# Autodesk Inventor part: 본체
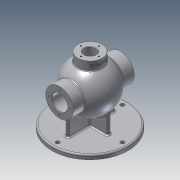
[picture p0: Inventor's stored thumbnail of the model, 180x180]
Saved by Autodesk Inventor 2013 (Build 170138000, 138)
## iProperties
Created: 2020-08
Part Number: 본체
Material: 알루미늄 6061
Document SubType Name: Sheet Metal
Designer: CADCOM
Density: 2.71 g/cm^3
Sheet Metal Rule: Default_mm
Mass: 1759.19 g
Surface Area: 1342.58 cm^2
Volume: 649.146 cm^3
Author: CADCOM
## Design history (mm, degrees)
sketch "스케치2"
  geometry: L1 (-27.958, -45.026)-(27.958, 45.026); A1 r 53 centre (0, 0) between (-27.958, -45.026) and (27.958, 45.026); 1 further point
  constraints: 2 end point, 2 point on circle, 1 centre point, 1 coincident, 1 midpoint
  dimensions: "d3" = 106 diameter of A1
revolve "회전2" sketch "스케치2" stored, may be unused: angle "d4" = 90 deg
node "작업 평면1"
sketch "스케치3"
  geometry: C1 r 31 at (0, 0); 1 further point
  constraints: 1 centre point, 1 coincident
  dimensions: "d6" = 62 diameter of C1
extrude "돌출1" join sketch "스케치3" stored distance "d7" = 10; taper "d8" = 0 deg
node "작업 평면2"
sketch "스케치4"
  geometry: C1 r 31 at (0, 0); 1 further point
  constraints: 1 centre point, 1 coincident
  dimensions: "d10" = 62 diameter of C1
extrude "돌출2" join sketch "스케치4" stored distance "d11" = 10; taper "d12" = 0 deg
sketch "스케치5"
  geometry: L1 (32.002, -28.72)-(-32.002, 28.72); A1 r 43 centre (0, 0) between (32.002, -28.72) and (-32.002, 28.72); 1 further point
  constraints: 2 end point, 2 point on circle, 1 centre point, 1 coincident, 1 midpoint
  dimensions: "d13" = 86 diameter of A1
revolve "회전3" sketch "스케치5" stored, may be unused: angle "d14" = 90 deg
sketch "스케치6"
  geometry: C1 r 31 at (0, 0) reference; C2 r 17.5 at (0, 0)
  constraints: 1 centre point, 1 coincident
  dimensions: "d15" = 35 diameter of C2
extrude "돌출3" cut sketch "스케치6" stored distance "d16" = 10; taper "d17" = 0 deg
node "작업 평면3"
sketch "스케치7"
  geometry: C1 r 27 at (0, 0); 1 further point
  constraints: 1 centre point, 1 coincident
  dimensions: "d19" = 54 diameter of C1
extrude "돌출4" join sketch "스케치7" stored distance "d20" = 10; taper "d21" = 0 deg
sketch "스케치8"
  geometry: C1 r 27 at (0, 0) reference; C2 r 13 at (0, 0)
  constraints: 1 centre point, 1 coincident
  dimensions: "d22" = 26 diameter of C2
extrude "돌출5" cut sketch "스케치8" stored distance "d23" = 10; taper "d24" = 0 deg
sketch "스케치9" dims "d25" = 48
  geometry: C1 r 17.5 at (0, 0) reference; C2 r 31 at (0, 0) reference; 2 further points
  constraints: 2 vertical alignment, 1 coincident, 2 other
hole "구멍1" sketch "스케치9" at (0, 24) diameter "d26" = 3.242; stored, may be unused: countersink angle "d30" = 90 deg, drill point angle "d32" = 118 deg; dims "d27" = 12, "d28" = 4, "d29" = 2, "d31" = 15
sketch "스케치10" dims "d36" = 40
  geometry: C1 r 13 at (0, 0) reference; C2 r 27 at (0, 0) reference; 2 further points
  constraints: 2 vertical alignment, 1 coincident, 2 other
hole "구멍2" sketch "스케치10" at (0, 20) diameter "d37" = 3.242; stored, may be unused: countersink angle "d41" = 90 deg, drill point angle "d43" = 118 deg; dims "d38" = 12, "d39" = 4, "d40" = 2, "d42" = 15
node "작업 평면4"
sketch "스케치11"
  geometry: C1 r 85 at (0, 0); 1 further point
  constraints: 1 centre point, 1 coincident
  dimensions: "d48" = 170 diameter of C1
extrude "돌출6" join sketch "스케치11" distance "d49" = 10; taper "d50" = 0 deg
sketch "스케치12"
  geometry: L1 (-52, 4)-(52, 4); L2 (52, 4)-(52, -4); L3 (52, -4)-(-52, -4); L4 (-52, -4)-(-52, 4); L5 (-4, 43)-(4, 43); L6 (4, 43)-(4, -43); L7 (4, -43)-(-4, -43); L8 (-4, -43)-(-4, 43); C1 r 85 at (0, 0) reference
  constraints: 16 end point, 4 parallel, 2 horizontal, 2 perpendicular
  dimensions: "d51" = 104 distance of L2.end L3.end; "d52" = 8 distance of L1.end L2.end; "d53" = 52 distance from line of L2 C1.centre; "d54" = 4 distance from line of C1.centre L1; "d55" = 8 distance of L6.end L7.end; "d56" = 86 distance of L5.end L6.end; "d57" = 43 distance from line of C1.centre L5; "d58" = 4 distance from line of C1.centre L6
extrude "돌출7" join sketch "스케치12" stored distance "d59" = 10; taper "d60" = 0 deg
sketch "스케치13" dims "d61" = 145
  geometry: C1 r 85 at (0, 0) reference; 2 further points
  constraints: 2 vertical alignment, 1 coincident, 2 other
hole "구멍3" sketch "스케치13" at (0, 72.5) diameter "d62" = 9; stored, may be unused: countersink angle "d66" = 90 deg, drill point angle "d68" = 118 deg; dims "d63" = 12, "d64" = 4, "d65" = 2, "d67" = 15
node "작업 평면5"
sketch "스케치14"
  geometry: L1 (-27, 65)-(27, 65) reference; L2 (-27, 45.607)-(27, 45.607) reference; L3 (27, 65)-(27, 45.607) reference; L4 (-27, 65)-(-27, 45.607) reference; 2 further points
  constraints: 1 other
  dimensions: "d74" = 9 distance from line of point (0, 56) L1; "d75" = 27 distance from line of L4 point (0, 56)
feature "엠보싱1" sketch "스케치14" dims "d11" = 10, "d12" = 0, "d76" = 0.5, "d77" = 0
node "작업 평면6"
chamfer "모따기1" distance "d82" = 1; stored, may be unused: second distance "d83" = 2, angle "d84" = 45 deg
fillet "모깎기1" dims "d85" = 3
fillet "모깎기2" dims "d86" = 3
fillet "모깎기3" dims "d87" = 3
fillet "모깎기4" dims "d88" = 3
fillet "모깎기5" dims "d89" = 3
node "작업 평면7"
sketch "스케치17"
  geometry: L1 (-1, -72)-(-1, -33.985) reference; L2 (-1, -72)-(1, -72) reference; L3 (1, -72)-(1, -33.985) reference; L4 (-63.403, -75)-(-6.196, -75) reference; L5 (-67.238, -85)-(-67.238, -78) reference; L6 (67.238, -85)-(-67.238, -85) reference; L7 (67.238, -78)-(67.238, -85) reference; L8 (6.196, -75)-(63.403, -75) reference; C1 r 17.5 at (0, 0) reference; C2 r 18.5 at (0, 0); A1 r 31 centre (0, 0) between (5.649, -30.481) and (-5.649, -30.481) reference; A2 r 34 centre (0, 0) between (-1, -33.985) and (1, -33.985) reference; 1 further point
  constraints: 1 centre point, 1 coincident, 6 other
  dimensions: "d91" = 37 diameter of C2
extrude "돌출9" cut sketch "스케치17" distance "d92" = 1.75; taper "d93" = 0 deg
node "솔리드2"
pattern_circular "원형 패턴1" dims angle "d34" = 360 deg
pattern_circular "원형 패턴2" dims angle "d45" = 360 deg
mirror "대칭1"
pattern_circular "원형 패턴3" dims angle "d70" = 360 deg
node "절단 모서리 투영2"
other parameters: "Thickness" = 0.5, "BendRadius" = 0.5 (= Thickness), "BendReliefWidth" = 0.5 (= Thickness), "BendReliefDepth" = 0.25 (= 0.5 x Thickness), "CornerReliefSize" = 2 (= 4 x Thickness), "SeamGap" = 0.01, "MinimumRemnant" = 1 (= 2 x Thickness), "TransitionRadius" = 0.5 (= BendRadius), "JacobiRadiusSize" = 0.5 (= BendRadius), "GapSize" = 0.5 (= Thickness), "d5" = 68, "d9" = -68, "d18" = 65, "d47" = -85, "d72" = 38, "d78" = -16, "d90" = -16
